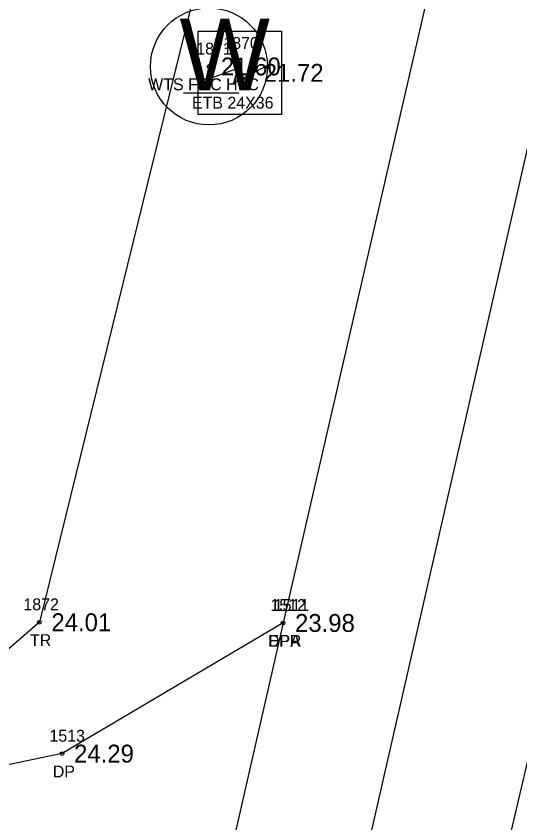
# Model space of a CAD drawing. Extents: x 2654414 to 2656963, y 761776 to 764965.
# Drawn here: x 2655582.6 to 2655624.8, y 762792.6 to 762860.3 of the extents above; entities that cross this region are included whole.
import ezdxf

# ---------------------------------------------------------------- set-up
doc = ezdxf.new("R2010")
doc.units = 0
for name, color, linetype in [('Default', 7, 'Continuous'), ('RD_EX_Driveway', 7, 'Continuous'), ('RD_EX_Driveway_txCode', 7, 'Continuous'), ('RD_EX_Road', 7, 'Continuous'), ('RD_EX_Road_txCode', 7, 'Continuous'), ('RD_EX_TX_Driveway_ELEV', 7, 'Continuous'), ('RD_EX_TX_Road_ELEV', 7, 'Continuous'), ('RD_EX_TX_UT_ELEV', 7, 'Continuous'), ('RD_EX_TX_VEG_ELEV', 7, 'Continuous'), ('RD_EX_UT', 7, 'Continuous'), ('RD_EX_UT_txCode', 7, 'Continuous'), ('RD_EX_VEG', 7, 'Continuous'), ('RD_EX_VEG_txCode', 7, 'Continuous'), ('RD_HC_Cl', 7, 'Continuous'), ('RD_SMD_Locator', 7, 'Continuous')]:
    doc.layers.add(name, color=color, linetype=linetype)

msp = doc.modelspace()

# ---------------------------------------------------------------- linework, layer by layer
at = {"layer": 'Default'}
msp.add_line((2656050.51, 764712.367), (2655383.263, 761787.511), dxfattribs=at)
at = {"layer": 'RD_EX_Driveway'}
msp.add_lwpolyline([(2655604.996, 762809.365), (2655586.467, 762798.406), (2655573.364, 762795.671), (2655559.244, 762787.47), (2655545.038, 762765.332), (2655541.015, 762760.719), (2655533.691, 762755.144), (2655505.037, 762752.17)], dxfattribs=at)
at = {"layer": 'RD_EX_Road'}
for points in [[(2655700.994, 763232.279), (2655693.552, 763198.573), (2655671.649, 763102.037), (2655649.038, 763001.061), (2655627.271, 762906.233), (2655604.996, 762809.365), (2655598.992, 762783.09), (2655583.655, 762714.137), (2655561.97, 762618.323), (2655556.356, 762593.843), (2655548.114, 762557.141), (2655540.102, 762522.478), (2655518.03, 762425.04), (2655496.479, 762329.558), (2655475.552, 762236.625), (2655473.199, 762226.142), (2655466.574, 762197.504), (2655460.058, 762168.164), (2655454.261, 762143.776), (2655432.5, 762049.878), (2655410.7, 761955.515), (2655388.166, 761858.426), (2655373.501, 761793.951)], [(2655670.037, 762995.178), (2655648.569, 762900.673), (2655631.27, 762824.032), (2655626.665, 762802.872), (2655621.781, 762781.907), (2655611.705, 762738.435), (2655604.931, 762708.622), (2655582.644, 762610.543), (2655576.456, 762583.319), (2655561.406, 762517.242), (2655539.154, 762414.805), (2655531.984, 762386.147), (2655517.984, 762324.295), (2655508.173, 762280.146), (2655501.462, 762251.601), (2655496.922, 762232.086), (2655477.204, 762144.974), (2655472.137, 762122.524), (2655453.741, 762045.099), (2655431.791, 761949.924), (2655409.76, 761853.25), (2655401.248, 761816.416), (2655394.612, 761787.366)]]:
    msp.add_lwpolyline(points, dxfattribs=at)
at = {"layer": 'RD_EX_UT'}
msp.add_line((2655596.649, 762853.842), (2655601.279, 762853.842), dxfattribs=at)
msp.add_lwpolyline([(2655597.87, 762852.012), (2655597.87, 762859.012), (2655604.87, 762859.012), (2655604.87, 762852.012)], close=True, dxfattribs=at)
msp.add_lwpolyline([(2655598.769, 762855.006), (2655601.191, 762855.906), (2655600.845, 762854.659), (2655603.89, 762856.252)], dxfattribs=at)
msp.add_circle((2655598.778, 762856.05), 4.908, dxfattribs=at)
at = {"layer": 'RD_EX_VEG'}
msp.add_lwpolyline([(2655677.341, 763211.225), (2655657.545, 763106.21), (2655584.566, 762809.424), (2655537.645, 762768.623), (2655489.103, 762755.63)], dxfattribs=at)
at = {"layer": 'RD_HC_Cl'}
msp.add_line((2656050.51, 764712.367), (2655383.263, 761787.511), dxfattribs=at)
at = {"layer": 'RD_SMD_Locator'}
for centre in [(2655598.778, 762856.05), (2655601.37, 762855.512), (2655584.566, 762809.424), (2655604.996, 762809.365), (2655604.996, 762809.365), (2655586.467, 762798.406)]:
    msp.add_circle(centre, 0.15, dxfattribs=at)

# ---------------------------------------------------------------- texts
at = {"layer": 'RD_EX_Driveway_txCode'}
for s, p in [('1512', (2655603.933, 762810.365)), ('DPA', (2655603.728, 762807.365)), ('1513', (2655585.404, 762799.406)), ('DP', (2655585.688, 762796.406))]:
    msp.add_text(s, height=1, dxfattribs=at).set_placement(p)
at = {"layer": 'RD_EX_Road_txCode'}
for s, p in [('1511', (2655604.216, 762810.365)), ('EPR', (2655603.767, 762807.365))]:
    msp.add_text(s, height=1, dxfattribs=at).set_placement(p)
at = {"layer": 'RD_EX_TX_Driveway_ELEV'}
for s, p in [('23.98', (2655605.996, 762808.615)), ('24.29', (2655587.467, 762797.656))]:
    msp.add_text(s, height=1.5, dxfattribs=at).set_placement(p)
at = {"layer": 'RD_EX_TX_Road_ELEV'}
msp.add_text('23.98', height=1.5, dxfattribs=at).set_placement((2655605.996, 762808.615))
at = {"layer": 'RD_EX_TX_UT_ELEV'}
for s, p in [('21.60', (2655599.778, 762855.3)), ('21.72', (2655603.37, 762854.762))]:
    msp.add_text(s, height=1.5, dxfattribs=at).set_placement(p)
at = {"layer": 'RD_EX_TX_VEG_ELEV'}
msp.add_text('24.01', height=1.5, dxfattribs=at).set_placement((2655585.566, 762808.674))
at = {"layer": 'RD_EX_UT'}
msp.add_text('W', height=6, dxfattribs=at).set_placement((2655596.313, 762854.049))
at = {"layer": 'RD_EX_UT_txCode'}
for s, p in [('1870', (2655599.985, 762857.512)), ('1871', (2655597.715, 762857.05)), ('WTS FOC HTC', (2655593.683, 762854.05)), ('ETB 24X36', (2655597.355, 762852.512))]:
    msp.add_text(s, height=1, dxfattribs=at).set_placement(p)
at = {"layer": 'RD_EX_VEG_txCode'}
for s, p in [('1872', (2655583.22, 762810.424)), ('TR', (2655583.771, 762807.424))]:
    msp.add_text(s, height=1, dxfattribs=at).set_placement(p)

doc.saveas('drawing.dxf')
